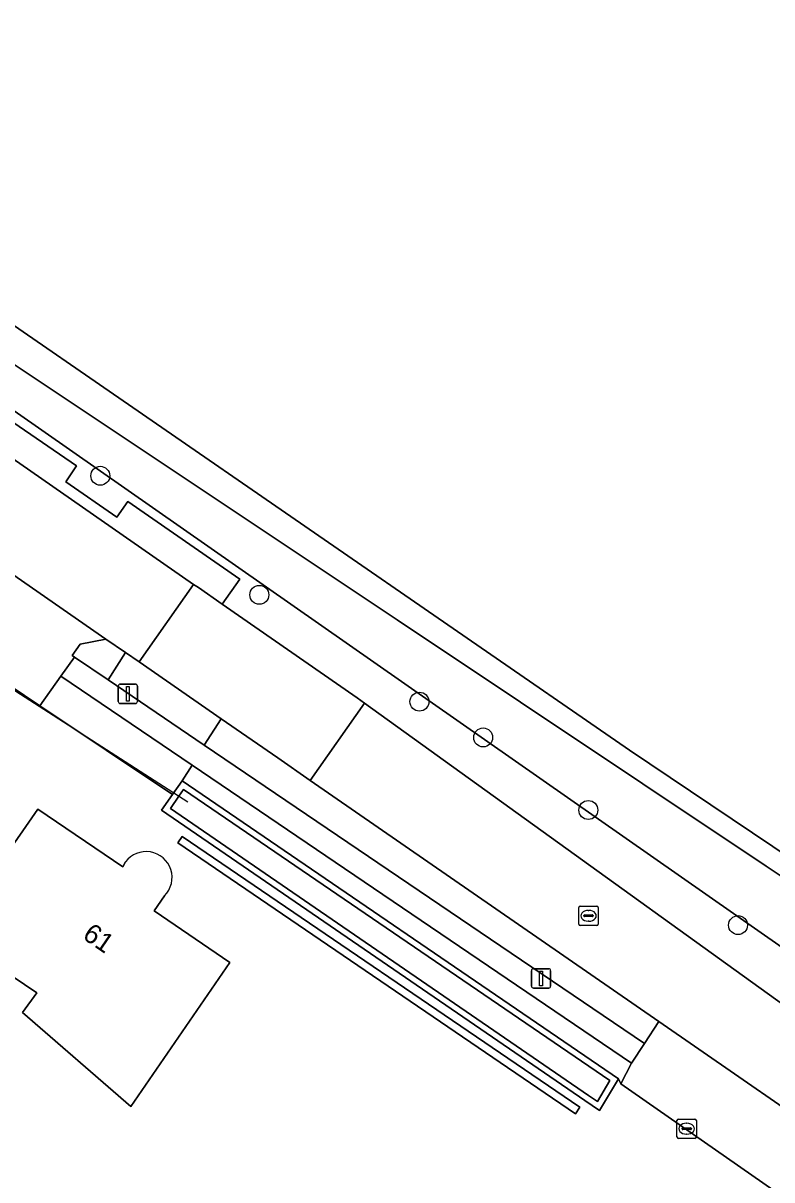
# Model space of a CAD drawing. Extents: x 163859 to 164644, y 379566 to 382155.
# Drawn here: x 164225.1 to 164263.8, y 381807.4 to 381867.2 of the extents above; entities that cross this region are included whole.
import ezdxf

# ---------------------------------------------------------------- set-up
doc = ezdxf.new("R2010")
doc.units = 0
for name, color, linetype in [('IMGEO_Boom', 7, 'Continuous'), ('IMGEO_Duiker', 7, 'Continuous'), ('IMGEO_Erf', 7, 'Continuous'), ('IMGEO_Grasland_agrarisch', 7, 'Continuous'), ('IMGEO_Grasland_overig', 7, 'Continuous'), ('IMGEO_Groenvoorziening', 7, 'Continuous'), ('IMGEO_Haag', 7, 'Continuous'), ('IMGEO_Kolk', 7, 'Continuous'), ('IMGEO_Lichtmast', 7, 'Continuous'), ('IMGEO_Oever', 7, 'Continuous'), ('IMGEO_Pand', 7, 'Continuous'), ('IMGEO_Pand_nummerreeks', 7, 'Continuous'), ('IMGEO_Parkeervlak_halfverhard', 7, 'Continuous'), ('IMGEO_Parkeervlak_open', 7, 'Continuous'), ('IMGEO_Rijbaan_lokaal_gesloten', 7, 'Continuous'), ('IMGEO_Rijbaan_lokaal_open', 7, 'Continuous'), ('IMGEO_Rioolput', 7, 'Continuous'), ('IMGEO_Voetpad_open', 7, 'Continuous'), ('IMGEO_Waterloop', 7, 'Continuous')]:
    doc.layers.add(name, color=color, linetype=linetype)

msp = doc.modelspace()

# ---------------------------------------------------------------- linework, layer by layer
at = {"layer": 'IMGEO_Boom'}
for centre in [(164229.12, 381843.797), (164237.333, 381837.646), (164245.6, 381832.13), (164248.894, 381830.283), (164254.325, 381826.534), (164262.056, 381820.59)]:
    msp.add_circle(centre, 0.489, dxfattribs=at)
at = {"layer": 'IMGEO_Duiker'}
msp.add_lwpolyline([(164217.268, 381837.469), (164218.022, 381836.985), (164233.632, 381826.955)], dxfattribs=at)
at = {"layer": 'IMGEO_Erf'}
for points in [[(164287.783, 381790.232), (164256.006, 381812.389), (164255.882, 381812.656), (164254.893, 381811.01), (164254.142, 381811.525), (164232.273, 381826.526), (164232.842, 381827.338), (164225.998, 381831.919), (164222.08, 381834.543), (164222.298, 381834.862), (164220.66, 381835.65), (164219.843, 381834.466), (164216.274, 381829.253), (164224.066, 381823.939), (164225.891, 381826.571), (164230.279, 381823.603), (164230.417, 381823.852)], [(164232.439, 381822.106), (164231.909, 381821.33), (164235.808, 381818.657), (164230.696, 381811.217), (164225.107, 381816.082), (164225.837, 381817.086), (164221.471, 381820.037), (164221.61, 381820.246), (164220.683, 381820.865), (164219.83, 381819.623), (164212.364, 381823.54), (164205.955, 381814.209), (164235.043, 381794.138), (164235.285, 381793.932), (164235.601, 381793.483), (164234.237, 381791.715), (164240.69, 381784.76), (164245.37, 381788.308), (164248.754, 381793.758), (164252.441, 381799.696), (164251.999, 381799.981), (164253.852, 381802.608)]]:
    msp.add_lwpolyline(points, dxfattribs=at)
msp.add_lwpolyline([(164233.126, 381824.841), (164233.352, 381825.171), (164253.894, 381811.182), (164253.669, 381810.851)], close=True, dxfattribs=at)
msp.add_arc((164231.487, 381823.048), 1.339, 315.31165, 143.06703, dxfattribs=at)
at = {"layer": 'IMGEO_Grasland_agrarisch'}
msp.add_lwpolyline([(164303.655, 381951.333), (164266.944, 381922.737), (164277.667, 381908.3), (164278.876, 381906.816), (164278.809, 381906.762), (164279.852, 381905.358), (164303.691, 381871.549), (164284.619, 381860.24), (164259.755, 381889.448), (164267.387, 381895.767), (164258.029, 381908.469), (164254.791, 381905.941), (164252.396, 381909.265), (164208.654, 381876.058), (164201.663, 381868.745), (164211.763, 381860.7), (164222.906, 381852.769), (164256.457, 381829.627), (164286.005, 381809.753), (164322.428, 381783.408), (164335.006, 381775.051), (164338.747, 381777.229), (164392.726, 381806.597)], dxfattribs=at)
at = {"layer": 'IMGEO_Grasland_overig'}
for points in [[(164286.005, 381809.753), (164256.457, 381829.627), (164222.906, 381852.769), (164211.763, 381860.7), (164201.663, 381868.745)], [(164200.241, 381867.209), (164203.607, 381864.729), (164212.773, 381858.254), (164219.743, 381853.042), (164219.769, 381853.023), (164223.061, 381850.617), (164244.45, 381836.352), (164263.512, 381823.639), (164264.597, 381822.915)]]:
    msp.add_lwpolyline(points, dxfattribs=at)
at = {"layer": 'IMGEO_Groenvoorziening'}
for points in [[(164261.825, 381821.183), (164221.968, 381849.023), (164223.061, 381850.617), (164219.769, 381853.023), (164219.553, 381852.482), (164219.129, 381851.953), (164218.468, 381851.741), (164217.304, 381852.35), (164212.541, 381855.181), (164205.239, 381860.42), (164197.592, 381866.161), (164196.931, 381866.161), (164195.529, 381866.611), (164195.052, 381867.457), (164195.268, 381868.391), (164195.29, 381868.489), (164195.394, 381868.583), (164194.945, 381868.909), (164183.031, 381877.576), (164180.902, 381879.968), (164176.8, 381882.795)], [(164175.458, 381878.387), (164203.483, 381859.285), (164205.181, 381858.114), (164214.31, 381851.815), (164215.15, 381853.032), (164227.892, 381844.304), (164227.341, 381843.488), (164229.978, 381841.659), (164230.539, 381842.463), (164236.331, 381838.448), (164235.41, 381837.168), (164242.387, 381832.326), (164242.758, 381832.059), (164272.361, 381810.742), (164289.667, 381798.436), (164312.339, 381782.446)], [(164324.169, 381774.363), (164359.822, 381750), (164360.25, 381749.708), (164360.489, 381750.103), (164360.511, 381750.139), (164361.118, 381751.14), (164362.264, 381753.03), (164362.019, 381753.203), (164361.428, 381751.86), (164361.269, 381751.975), (164350.837, 381759.485), (164291.421, 381800.511), (164261.825, 381821.183)]]:
    msp.add_lwpolyline(points, dxfattribs=at)
for points in [[(164230.42, 381834.663), (164229.404, 381835.36), (164228.079, 381835.092), (164227.67, 381834.52), (164227.793, 381834.436), (164229.527, 381833.256)], [(164239.966, 381828.066), (164238.288, 381829.227), (164235.361, 381831.249), (164234.476, 381829.885), (164257.217, 381814.474), (164257.966, 381815.614)], [(164233.864, 381828.855), (164233.34, 381828.049), (164255.882, 381812.656), (164256.006, 381812.389), (164256.552, 381813.463)], [(164233.352, 381825.171), (164233.126, 381824.841), (164253.669, 381810.851), (164253.894, 381811.182)]]:
    msp.add_lwpolyline(points, close=True, dxfattribs=at)
at = {"layer": 'IMGEO_Haag'}
msp.add_lwpolyline([(164233.352, 381825.171), (164233.126, 381824.841), (164253.669, 381810.851), (164253.894, 381811.182)], close=True, dxfattribs=at)
at = {"layer": 'IMGEO_Kolk'}
for p, q in [((164258.978, 381810.577), (164259.83, 381810.577)), ((164258.903, 381809.651), (164258.903, 381810.503)), ((164259.162, 381810.071), (164259.162, 381810.083)), ((164259.6, 381810.034), (164259.202, 381810.034)), ((164259.205, 381810.12), (164259.603, 381810.12)), ((164259.391, 381810.357), (164259.416, 381810.357)), ((164259.646, 381810.083), (164259.646, 381810.071)), ((164259.904, 381810.503), (164259.904, 381809.651)), ((164259.83, 381809.577), (164258.978, 381809.577)), ((164259.414, 381809.797), (164259.389, 381809.797))]:
    msp.add_line(p, q, dxfattribs=at)
for points in [[(164258.978, 381810.577), (164259.83, 381810.577)], [(164258.903, 381809.651), (164258.903, 381810.503)], [(164259.904, 381810.503), (164259.904, 381809.651)], [(164259.83, 381809.577), (164258.978, 381809.577)]]:
    msp.add_lwpolyline(points, dxfattribs=at)
for centre, radius, start, end in [((164258.98, 381810.501), 0.0765, 91.55205, 178.44795), ((164258.98, 381810.501), 0.0765, 91.55205, 178.44795), ((164259.828, 381810.501), 0.0765, 1.55205, 88.44795), ((164259.828, 381810.501), 0.0765, 1.55205, 88.44795), ((164259.202, 381810.08), 0.0403, 85.87752, 175.75265), ((164259.199, 381810.07), 0.0366, 178.93798, 274.71019), ((164259.603, 381810.077), 0.043, 264.86636, 352.45326), ((164259.607, 381810.082), 0.0386, 1.73085, 96.63898), ((164258.98, 381809.653), 0.0765, 181.55205, 268.44795), ((164258.98, 381809.653), 0.0765, 181.55205, 268.44795), ((164259.828, 381809.653), 0.0765, 271.55205, 358.44795), ((164259.828, 381809.653), 0.0765, 271.55205, 358.44795)]:
    msp.add_arc(centre, radius, start, end, dxfattribs=at)
for centre, major_axis, ratio, start_param, end_param in [((164259.39, 381810.077), (-0.387, 0.002), 0.722429, 4.712389, 7.853982), ((164259.415, 381810.077), (-0.39, 0.002), 0.717154, 1.570796, 4.712389)]:
    msp.add_ellipse(centre, major_axis=major_axis, ratio=ratio, start_param=start_param, end_param=end_param, dxfattribs=at)
at = {"layer": 'IMGEO_Lichtmast'}
for p, q in [((164230.049, 381832.135), (164230.049, 381832.935)), ((164230.049, 381832.935), (164230.049, 381832.135)), ((164230.149, 381833.035), (164230.939, 381833.035)), ((164230.939, 381833.035), (164230.149, 381833.035)), ((164231.039, 381832.935), (164231.039, 381832.135)), ((164231.039, 381832.135), (164231.039, 381832.935)), ((164230.939, 381832.035), (164230.149, 381832.035)), ((164230.149, 381832.035), (164230.939, 381832.035)), ((164251.489, 381818.337), (164252.279, 381818.337)), ((164252.279, 381818.337), (164251.489, 381818.337)), ((164251.389, 381817.437), (164251.389, 381818.237)), ((164251.389, 381818.237), (164251.389, 381817.437)), ((164252.379, 381818.237), (164252.379, 381817.437)), ((164252.379, 381817.437), (164252.379, 381818.237)), ((164252.279, 381817.337), (164251.489, 381817.337)), ((164251.489, 381817.337), (164252.279, 381817.337))]:
    msp.add_line(p, q, dxfattribs=at)
for points in [[(164230.469, 381832.91), (164230.619, 381832.91), (164230.619, 381832.16), (164230.469, 381832.16), (164230.469, 381832.91)], [(164251.809, 381818.212), (164251.959, 381818.212), (164251.959, 381817.462), (164251.809, 381817.462), (164251.809, 381818.212)]]:
    msp.add_lwpolyline(points, dxfattribs=at)
for centre, start, end in [((164230.149, 381832.935), 90, 180), ((164230.149, 381832.935), 90, 180), ((164230.939, 381832.935), 0, 90), ((164230.939, 381832.935), 360, 90), ((164230.149, 381832.135), 180, 270), ((164230.149, 381832.135), 180, 270), ((164230.939, 381832.135), 270, 0), ((164230.939, 381832.135), 270, 0), ((164251.489, 381818.237), 90, 180), ((164251.489, 381818.237), 90, 180), ((164252.279, 381818.237), 0, 90), ((164252.279, 381818.237), 360, 90), ((164251.489, 381817.437), 180, 270), ((164251.489, 381817.437), 180, 270), ((164252.279, 381817.437), 270, 0), ((164252.279, 381817.437), 270, 0)]:
    msp.add_arc(centre, 0.1, start, end, dxfattribs=at)
at = {"layer": 'IMGEO_Oever'}
for points in [[(164233.34, 381828.049), (164232.842, 381827.338), (164232.273, 381826.526), (164254.142, 381811.525), (164254.893, 381811.01), (164255.882, 381812.656)], [(164233.424, 381827.588), (164255.434, 381812.558), (164254.79, 381811.485), (164254.331, 381811.8), (164232.739, 381826.61), (164233.183, 381827.244)]]:
    msp.add_lwpolyline(points, close=True, dxfattribs=at)
at = {"layer": 'IMGEO_Pand'}
msp.add_lwpolyline([(164230.417, 381823.852), (164230.279, 381823.603), (164225.891, 381826.571), (164224.066, 381823.939), (164216.274, 381829.253), (164212.364, 381823.54), (164219.83, 381819.623), (164220.683, 381820.865), (164221.61, 381820.246), (164221.471, 381820.037), (164225.837, 381817.086), (164225.107, 381816.082), (164230.696, 381811.217), (164235.808, 381818.657), (164231.909, 381821.33), (164232.439, 381822.106)], dxfattribs=at)
msp.add_arc((164231.487, 381823.048), 1.339, 315.31165, 143.06703, dxfattribs=at)
at = {"layer": 'IMGEO_Parkeervlak_halfverhard'}
msp.add_lwpolyline([(164215.15, 381853.032), (164214.31, 381851.815), (164218.242, 381849.102), (164233.939, 381838.189), (164234.184, 381838.019), (164235.41, 381837.168), (164236.331, 381838.448), (164230.539, 381842.463), (164229.978, 381841.659), (164227.341, 381843.488), (164227.892, 381844.304)], close=True, dxfattribs=at)
at = {"layer": 'IMGEO_Parkeervlak_open'}
for points in [[(164231.119, 381834.18), (164230.42, 381834.663), (164229.527, 381833.256), (164234.476, 381829.885), (164235.361, 381831.249)], [(164274.046, 381804.404), (164268.514, 381808.317), (164257.966, 381815.614), (164257.217, 381814.474), (164256.552, 381813.463), (164256.006, 381812.389), (164287.783, 381790.232), (164288.111, 381790.003), (164288.679, 381789.603), (164288.789, 381789.762), (164289.678, 381791.017), (164290.39, 381792.012), (164290.856, 381792.662), (164287.307, 381795.184)]]:
    msp.add_lwpolyline(points, close=True, dxfattribs=at)
at = {"layer": 'IMGEO_Rijbaan_lokaal_gesloten'}
for points in [[(164218.242, 381849.102), (164214.31, 381851.815), (164205.181, 381858.114), (164202.562, 381853.773), (164213.948, 381845.959), (164215.248, 381845.088), (164224.041, 381839.088), (164229.404, 381835.36), (164230.42, 381834.663), (164231.119, 381834.18), (164233.939, 381838.189)], [(164235.41, 381837.168), (164234.184, 381838.019), (164233.939, 381838.189), (164231.119, 381834.18), (164235.361, 381831.249), (164238.288, 381829.227), (164239.966, 381828.066), (164242.758, 381832.059), (164242.387, 381832.326)]]:
    msp.add_lwpolyline(points, close=True, dxfattribs=at)
msp.add_lwpolyline([(164289.667, 381798.436), (164272.361, 381810.742), (164242.758, 381832.059), (164239.966, 381828.066), (164257.966, 381815.614), (164268.514, 381808.317), (164274.046, 381804.404), (164287.307, 381795.184), (164290.856, 381792.662), (164308.664, 381780.116)], dxfattribs=at)
at = {"layer": 'IMGEO_Rijbaan_lokaal_open'}
msp.add_lwpolyline([(164224.041, 381839.088), (164224.271, 381837.825), (164223.813, 381837.103), (164223.128, 381836.076), (164222.298, 381834.862), (164222.08, 381834.543), (164225.998, 381831.919), (164227.089, 381833.448), (164227.793, 381834.436), (164227.67, 381834.52), (164228.079, 381835.092), (164229.404, 381835.36)], close=True, dxfattribs=at)
at = {"layer": 'IMGEO_Rioolput'}
for p, q in [((164253.835, 381820.647), (164253.835, 381821.499)), ((164253.91, 381821.573), (164254.762, 381821.573)), ((164254.323, 381821.353), (164254.348, 381821.353)), ((164254.836, 381821.499), (164254.836, 381820.647)), ((164254.094, 381821.067), (164254.094, 381821.079)), ((164254.532, 381821.03), (164254.134, 381821.03)), ((164254.137, 381821.116), (164254.535, 381821.116)), ((164254.346, 381820.793), (164254.321, 381820.793)), ((164254.578, 381821.079), (164254.578, 381821.067)), ((164254.762, 381820.573), (164253.91, 381820.573))]:
    msp.add_line(p, q, dxfattribs=at)
for points in [[(164253.835, 381820.647), (164253.835, 381821.499)], [(164253.91, 381821.573), (164254.762, 381821.573)], [(164254.836, 381821.499), (164254.836, 381820.647)], [(164254.762, 381820.573), (164253.91, 381820.573)]]:
    msp.add_lwpolyline(points, dxfattribs=at)
for centre, radius, start, end in [((164253.912, 381821.497), 0.0765, 91.55205, 178.44795), ((164253.912, 381821.497), 0.0765, 91.55205, 178.44795), ((164254.76, 381821.497), 0.0765, 1.55205, 88.44795), ((164254.76, 381821.497), 0.0765, 1.55205, 88.44795), ((164254.134, 381821.076), 0.0403, 85.87752, 175.75265), ((164254.131, 381821.066), 0.0366, 178.93798, 274.71019), ((164254.535, 381821.073), 0.043, 264.86636, 352.45326), ((164254.539, 381821.078), 0.0386, 1.73085, 96.63898), ((164253.912, 381820.649), 0.0765, 181.55205, 268.44795), ((164253.912, 381820.649), 0.0765, 181.55205, 268.44795), ((164254.76, 381820.649), 0.0765, 271.55205, 358.44795), ((164254.76, 381820.649), 0.0765, 271.55205, 358.44795)]:
    msp.add_arc(centre, radius, start, end, dxfattribs=at)
for centre, major_axis, ratio, start_param, end_param in [((164254.322, 381821.073), (-0.387, 0.002), 0.722429, 4.712389, 7.853982), ((164254.347, 381821.073), (-0.39, 0.002), 0.717154, 1.570796, 4.712389)]:
    msp.add_ellipse(centre, major_axis=major_axis, ratio=ratio, start_param=start_param, end_param=end_param, dxfattribs=at)
at = {"layer": 'IMGEO_Voetpad_open'}
for points in [[(164234.476, 381829.885), (164229.527, 381833.256), (164227.793, 381834.436), (164227.089, 381833.448), (164233.864, 381828.855), (164256.552, 381813.463), (164257.217, 381814.474)], [(164227.089, 381833.448), (164225.998, 381831.919), (164232.842, 381827.338), (164233.34, 381828.049), (164233.864, 381828.855)]]:
    msp.add_lwpolyline(points, close=True, dxfattribs=at)
at = {"layer": 'IMGEO_Waterloop'}
for points in [[(164293.413, 381802.563), (164264.597, 381822.915), (164263.512, 381823.639), (164244.45, 381836.352), (164223.061, 381850.617), (164221.968, 381849.023), (164261.825, 381821.183), (164291.421, 381800.511), (164350.837, 381759.485), (164361.269, 381751.975), (164361.428, 381751.86), (164362.019, 381753.203), (164361.552, 381753.543), (164351.545, 381760.837), (164333.203, 381774.002)], [(164233.424, 381827.588), (164233.183, 381827.244), (164232.739, 381826.61), (164254.331, 381811.8), (164254.79, 381811.485), (164255.434, 381812.558)]]:
    msp.add_lwpolyline(points, close=True, dxfattribs=at)

# ---------------------------------------------------------------- texts
at = {"layer": 'IMGEO_Pand_nummerreeks'}
msp.add_text('61', height=1, rotation=325.56701, dxfattribs=at).set_placement((164228.147, 381819.932))

doc.saveas('drawing.dxf')
